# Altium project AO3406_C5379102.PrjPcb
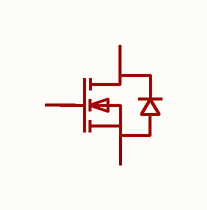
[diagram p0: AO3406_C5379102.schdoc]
1 sheet, 1 parts. Net scope: global (net labels, ports and power ports of the same name join across sheets).

## Sheet AO3406_C5379102.schdoc
size 127 x 101 mm

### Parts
Q?  ao3406_c5379102  [SOT-23-3_L2.9-W1.6-P1.90-LS2.8-BR]  (value not drawn)

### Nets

Not connected (* = marked no-connect by the designer): Q? 1(G) 2(S) 3(D)

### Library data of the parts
Q? = ao3406_c5379102: 数量:1个N沟道;漏源电压(Vdss):30V;连续漏极电流(Id):3.5A;导通电阻(RDS(on)):35mΩ@10V;耗散功率(Pd):278mW;阈值电压(Vgs(th)):1.5V;; Manufacturer: MSKSEMI(美森科); ManufacturerPart: AO3406; AddInBom: yes; ModelId: 89cb27a44ab2466697082bb9fd73a7d0; ModelName: SOT-23-3L_L2.9-W1.6-H1.1-LS2.8-P0.95; ModelTransform: 114.173,110.236,0,90,0,0,0,0,0; Number: 1个N沟道; Drain to Source Voltage: 30V; Current - Continuous Drain(Id): 3.5A; Pd - Power Dissipation: 278mW; Gate Threshold Voltage (Vgs(th)): 1.5V; Gate Charge(Qg): 3.1nC@10V; Input Capacitance(Ciss): 245pF; Reverse Transfer Capacitance (Crss@Vds): 78pF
